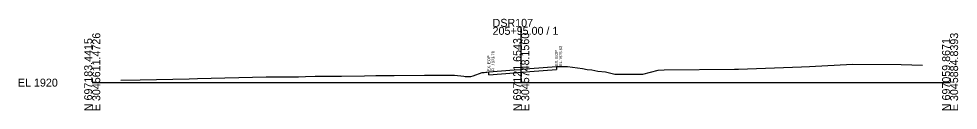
# Model space of a CAD drawing. Extents: x -26 to 19003, y -31 to 24541.
# Drawn here: x 1974.3 to 2302.8, y 6990.3 to 7022.4 of the extents above; entities that cross this region are included whole.
import ezdxf

# ---------------------------------------------------------------- set-up
doc = ezdxf.new("R2010")
doc.units = 0
for name, color, linetype in [('DESIGN - SHEET - Light Grid', 7, 'Continuous'), ('SURVEY - GROUND - Existing Pavement Layer', 7, 'Continuous'), ('SURVEY - GROUND - Existing Pavement Text', 7, 'Continuous'), ('SURVEY - GROUND - Top of Ground', 7, 'Continuous')]:
    doc.layers.add(name, color=color, linetype=linetype)

msp = doc.modelspace()

# ---------------------------------------------------------------- linework, layer by layer
at = {"layer": 'DESIGN - SHEET - Light Grid'}
for p, q in [((2150, 7000), (2150, 7019.57)), ((2000, 7000), (2150, 7000)), ((2150, 7000), (2300, 7000))]:
    msp.add_line(p, q, dxfattribs=at)
at = {"layer": 'SURVEY - GROUND - Existing Pavement Layer'}
for p, q in [((2153.04, 7003.9), (2162.33, 7004.63)), ((2162.33, 7005.63), (2162.33, 7004.63)), ((2138.67, 7002.78), (2138.67, 7003.78)), ((2138.67, 7002.78), (2147.52, 7003.46)), ((2147.52, 7003.46), (2150, 7003.66)), ((2150, 7003.66), (2150.62, 7003.71)), ((2150.62, 7003.71), (2153.04, 7003.9))]:
    msp.add_line(p, q, dxfattribs=at)
at = {"layer": 'SURVEY - GROUND - Top of Ground'}
msp.add_lwpolyline([(2010.04, 7000.82), (2016.77, 7000.96), (2033.84, 7001.37), (2036.79, 7001.45), (2060.81, 7002.07), (2066.48, 7002.03), (2070.49, 7002.05), (2072.11, 7002.06), (2074.57, 7002.19), (2077.95, 7002.28), (2083.24, 7002.29), (2087.19, 7002.26), (2095.22, 7002.43), (2099.15, 7002.48), (2105.53, 7002.48), (2116.16, 7002.58), (2118.96, 7002.65), (2121.53, 7002.6), (2126.68, 7002.6), (2129.95, 7002.22), (2130.42, 7002.14), (2130.74, 7002.15), (2132.44, 7002.16), (2133.25, 7002.43), (2136.33, 7003.52), (2137.1, 7003.61), (2137.59, 7003.65), (2138.04, 7003.7), (2138.67, 7003.78), (2147.52, 7004.46), (2150, 7004.66), (2150.62, 7004.71), (2153.04, 7004.9), (2162.33, 7005.63), (2163.54, 7005.7), (2164.13, 7005.7), (2166.15, 7005.66), (2171.41, 7005), (2173.04, 7004.65), (2174.71, 7004.5), (2176.77, 7003.99), (2179.46, 7003.73), (2182.81, 7003.02), (2187.99, 7002.95), (2192.52, 7003), (2197.9, 7004.39), (2199.95, 7004.5), (2224.55, 7004.71), (2225.44, 7004.74), (2225.98, 7004.75), (2248.06, 7005.56), (2250.82, 7005.64), (2265.84, 7006.52), (2282.9, 7006.41), (2290.35, 7006.18)], dxfattribs=at)

# ---------------------------------------------------------------- texts
at = {"layer": 'DESIGN - SHEET - Light Grid'}
for s, p in [('DSR107', (2140, 7019.57)), ('205+95.00 / 1', (2140, 7016.77)), ('EL 1920', (1974, 6998.6))]:
    msp.add_text(s, height=2.8, dxfattribs=at).set_placement(p)
for s, p in [('N 697183.4415', (2000, 6990)), ('E 3045611.4726', (2002.8, 6990)), ('N 697121.6543', (2150, 6990)), ('E 3045748.1560', (2152.8, 6990)), ('N 697059.8671', (2300, 6990)), ('E 3045884.8393', (2302.8, 6990))]:
    msp.add_text(s, height=2.8, rotation=90, dxfattribs=at).set_placement(p)
at = {"layer": 'SURVEY - GROUND - Existing Pavement Text'}
for s, p in [('EX. EOP', (2162.83, 7005.83)), ('EL.1925.63', (2164.33, 7005.83)), ('EX. EOP', (2139.17, 7003.98)), ('EL.1923.78', (2140.67, 7003.98))]:
    msp.add_text(s, height=1, rotation=90, dxfattribs=at).set_placement(p)

doc.saveas('drawing.dxf')
